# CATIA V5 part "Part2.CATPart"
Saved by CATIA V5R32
Part number: Part2
Bounding box of the stored display mesh (mm): x -12.5 to 12.5, y -12.31 to 12.31, z 0 to 5
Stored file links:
  D:\PROJECTS\Project 2022\CATIA V5 6R 2022\Resources\Part Files\c16_catia_v5_6r2022_prt\Planer Joint-(Fig16-33)\Part2.CATPart
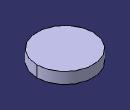
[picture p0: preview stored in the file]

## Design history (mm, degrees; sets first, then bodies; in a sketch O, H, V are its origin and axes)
Body1 (main body)
  Sketch1 on xy-plane, origin (0, 0, 0), H (1, 0, 0), V (0, 1, 0)
    circle A1 centre (0, 0) radius 12.5
    point P1 (0, 12.5)
    radius A1 = 12.5
    coincidence: A1 P1, P1 V
  Pad1: profile Sketch1, direction (0, 0, 1), length 5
